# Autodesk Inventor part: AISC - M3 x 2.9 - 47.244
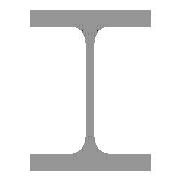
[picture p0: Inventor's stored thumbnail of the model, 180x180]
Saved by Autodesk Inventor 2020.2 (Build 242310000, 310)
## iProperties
Created: 2019-01
Part Number: AISC - M3 x 2.9 - 47.244
Material: Steel, Mild
Description: M-Shape
Document SubType Name: Modeling
Standard: ANSI
Designer: thira
Standards Organization: ANSI
Language: en-US
Size Designation: M3 x 2.9
Categories: <MemberInstance><Categories><Category DisplayName="Structural Shapes" InternalName="089c4875-fa83-4c05-b084-43b9cc11f5ed" Mnemonic="GRDR"><CategoryParameter Dis
Stock Number: M3 x 2.9
Density: 7.85 g/cm^3
Appearance: Semi-Polished
_CCFamilyMember: 14
_CCFamilyDisplayName: ANSI M - M-Shape — Sizes in parentheses have been withdrawn
_FrameMemberDoc: Frame Member File
_Version: 15.0.0
_GetPNFromCC: 1
G_L: 47.244 in
G_W: 2.250 in
G_H: 3.000 in
IsCustomPart: 1
Author: thira
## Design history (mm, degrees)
node "Start plane"
node "End plane"
sketch "Sketch"
  geometry: L1 (-28.575, -38.1)-(-28.575, -34.798); L2 (-28.575, -34.798)-(-10.541, -34.798); L3 (-1.143, -25.4)-(-1.143, 0); L4 (-1.143, 0)-(0, 0); L5 (0, 0)-(0, -38.1); L6 (0, -38.1)-(-28.575, -38.1); L7 (-60, 0)-(80, 0); L8 (0, -60)-(0, 80); L9 (28.575, -38.1)-(28.575, -34.798); L10 (28.575, -34.798)-(10.541, -34.798); L11 (0, -38.1)-(28.575, -38.1); L12 (1.143, -25.4)-(1.143, 0); L13 (1.143, 0)-(0, 0); L14 (-28.575, 38.1)-(-28.575, 34.798); L15 (0, 38.1)-(-28.575, 38.1); L16 (0, 38.1)-(28.575, 38.1); L17 (28.575, 34.798)-(10.541, 34.798); L18 (-28.575, 34.798)-(-10.541, 34.798); L19 (1.143, 25.4)-(1.143, 0); L20 (-1.143, 25.4)-(-1.143, 0); L21 (28.575, 38.1)-(28.575, 34.798); L22 (0, 108.7)-(0, -92.2) reference; L23 (-92.2, 0)-(108.7, 0) reference; A1 r 9.398 centre (-10.541, 25.4) between (-1.143, 25.4) and (-10.541, 34.798); A2 r 9.398 centre (10.541, 25.4) between (10.541, 34.798) and (1.143, 25.4); A3 r 9.398 centre (10.541, -25.4) between (1.143, -25.4) and (10.541, -34.798); A4 r 9.398 centre (-10.541, -25.4) between (-10.541, -34.798) and (-1.143, -25.4); 4 further points
  constraints: 42 end point, 11 symmetric about line, 8 point on circle, 8 point on line, 8 tangent, 4 centre point, 4 collinear, 4 parallel, 3 equal radius, 1 perpendicular, 1 vertical, 13 other
  dimensions: "d1" = 38.1 vertical distance of L1.start L3.end (= 0.5 x G_H); "d2" = 3.302 distance between parallel lines of L2 L6 (= G_T1); "d3" = 28.575 distance from line of L5.end L1 (= 0.5 x G_W); "d4" = 1.143 distance between parallel lines of L5 L3 (= 0.5 x G_T); "d13" = 9.398 radius of A1 (= G_IR)
extrude "Body" new body sketch "Sketch" stored distance "d5" = 1200 (= G_L); taper "d6" = 0 deg
node "Driven Length"
  sketch "Sketch4"
    geometry: L1 (0, 0)-(10, 0) reference
    constraints: 2 end point, 1 horizontal
  workplane "Work Plane3"
  sketch "Sketch5"
    geometry: L1 (-2, 0)-(12, 0) reference; L2 (-2, 1200)-(12, 1200) reference
    dimensions: "d15" = 1200 distance between parallel lines of L1 L2 (derived)
body "Solid1"
other parameters: "G_W" = 57.15 [user parameter; used in 1 equation term], "G_H" = 76.2 [user parameter; used in 1 equation term], "G_T" = 2.286 [user parameter; used in 1 equation term], "G_T1" = 3.302 [user parameter; used in 1 equation term], "G_IR" = 9.398 [user parameter; used in 1 equation term], "G_L" = 1200 (= d15) [user parameter; used in 1 equation term], "G_OFFSET_START" = 0 [user parameter; used in 1 equation term], "G_OFFSET_END" = 0 [user parameter; used in 1 equation term], "d11" = 0 (computed from G_OFFSET_START), "d12" = 1200 (= G_OFFSET_END + B_L), "B_L" = 1200 [user parameter; used in 1 equation term], "d14" = 90 deg
